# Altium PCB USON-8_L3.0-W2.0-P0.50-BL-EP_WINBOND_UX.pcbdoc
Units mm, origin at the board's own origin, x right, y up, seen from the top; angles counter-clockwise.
Board outline 15.05 x 16.42 mm, 2 copper layers (Top Layer, Bottom Layer), stack 0 mm thick; 1 components, 0 nets, 9 pads, 0 vias.
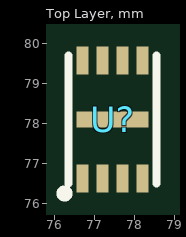
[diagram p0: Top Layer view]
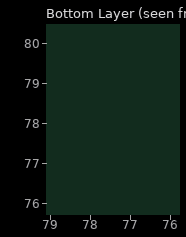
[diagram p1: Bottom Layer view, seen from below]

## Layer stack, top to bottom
Top Layer: signal copper (thickness not stored)
Bottom Layer: signal copper (thickness not stored)

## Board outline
84.901,69.85 69.85,69.85 69.85,86.274 84.901,86.274

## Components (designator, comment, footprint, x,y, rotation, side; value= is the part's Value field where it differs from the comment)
U? "" USON-8_L3.0-W2.0-P0.50-BL-EP_WINBOND_UX 77.451,78.101 r0 top

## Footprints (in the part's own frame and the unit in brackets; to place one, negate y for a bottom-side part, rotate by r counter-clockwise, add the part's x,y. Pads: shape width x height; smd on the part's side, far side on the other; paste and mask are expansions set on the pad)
USON-8_L3.0-W2.0-P0.50-BL-EP_WINBOND_UX [mm]
  rect 0.3x0.7 smd: 1(-0.75,-1.473) 2(-0.25,-1.473) 3(0.25,-1.473) 4(0.75,-1.473) 5(0.75,1.473) 6(0.25,1.473) 7(-0.25,1.473) 8(-0.75,1.473)
  rect 1.8x0.4 smd: 9(0,0)
  silkscreen extent -1.25,-1.9 1.1,1.6

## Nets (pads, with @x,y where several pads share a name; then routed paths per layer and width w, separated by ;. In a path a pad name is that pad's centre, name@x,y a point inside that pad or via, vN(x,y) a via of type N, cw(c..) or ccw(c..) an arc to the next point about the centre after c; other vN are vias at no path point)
pads on no net: U?.1 U?.2 U?.3 U?.4 U?.5 U?.6 U?.7 U?.8 U?.9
